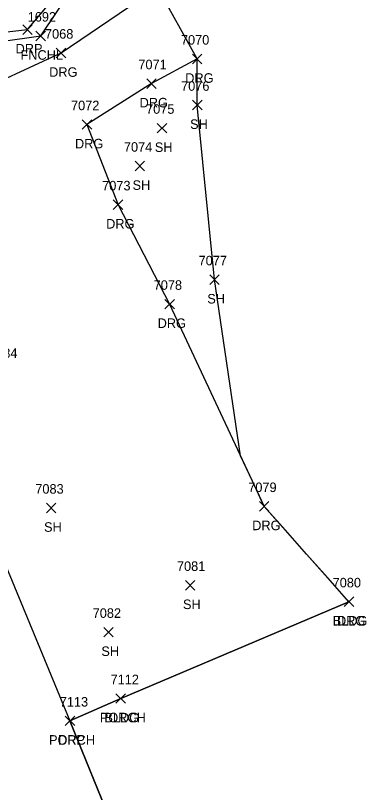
# Model space of a CAD drawing. Extents: x 1769141 to 1770911, y 735471 to 741449.
# Drawn here: x 1770390.5 to 1770464.1, y 736349.6 to 736512.6 of the extents above; entities that cross this region are included whole.
import ezdxf

# ---------------------------------------------------------------- set-up
doc = ezdxf.new("R2010")
doc.units = 0
for name, color, linetype in [('L_A', 7, 'Continuous'), ('L_I', 7, 'Continuous'), ('L_TIC', 7, 'Continuous'), ('LBC', 7, 'Continuous'), ('LBF', 7, 'Continuous'), ('LFNC', 7, 'Continuous'), ('LSOGP', 7, 'Continuous'), ('R_A', 7, 'Continuous'), ('R_I', 7, 'Continuous'), ('R_TIC', 7, 'Continuous'), ('RDG', 7, 'Continuous'), ('RDP', 7, 'Continuous')]:
    doc.layers.add(name, color=color, linetype=linetype)

msp = doc.modelspace()

# ---------------------------------------------------------------- linework, layer by layer
at = {"layer": 'L_TIC'}
for points in [[(1770394.78, 736507.31), (1770396.78, 736509.31)], [(1770396.78, 736507.31), (1770394.78, 736509.31)], [(1770427.63, 736492.8), (1770429.63, 736494.8)], [(1770429.63, 736492.8), (1770427.63, 736494.8)], [(1770420.22, 736487.97), (1770422.22, 736489.97)], [(1770422.22, 736487.97), (1770420.22, 736489.97)], [(1770415.56, 736480.02), (1770417.56, 736482.02)], [(1770417.56, 736480.02), (1770415.56, 736482.02)], [(1770431.24, 736456.18), (1770433.24, 736458.18)], [(1770433.24, 736456.18), (1770431.24, 736458.18)], [(1770396.98, 736408.29), (1770398.98, 736410.29)], [(1770398.98, 736408.29), (1770396.98, 736410.29)], [(1770426.13, 736392.08), (1770428.13, 736394.08)], [(1770428.13, 736392.08), (1770426.13, 736394.08)], [(1770459.45, 736388.63), (1770461.45, 736390.63)], [(1770461.45, 736388.63), (1770459.45, 736390.63)], [(1770409.01, 736382.24), (1770411.01, 736384.24)], [(1770411.01, 736382.24), (1770409.01, 736384.24)], [(1770411.55, 736368.32), (1770413.55, 736370.32)], [(1770413.55, 736368.32), (1770411.55, 736370.32)], [(1770411.55, 736368.32), (1770413.55, 736370.32)], [(1770413.55, 736368.32), (1770411.55, 736370.32)], [(1770400.9, 736363.63), (1770402.9, 736365.63)], [(1770402.9, 736363.63), (1770400.9, 736365.63)]]:
    msp.add_lwpolyline(points, dxfattribs=at)
at = {"layer": 'LBC'}
msp.add_lwpolyline([(1770460.45, 736389.63), (1770412.55, 736369.32)], dxfattribs=at)
at = {"layer": 'LBF'}
msp.add_lwpolyline([(1770412.55, 736369.32), (1770401.9, 736364.63), (1770411.08, 736342.09)], dxfattribs=at)
at = {"layer": 'LFNC'}
msp.add_lwpolyline([(1770354.72, 736502.49), (1770395.78, 736508.31), (1770402.62, 736518.61), (1770411.86, 736523.52)], dxfattribs=at)
at = {"layer": 'LSOGP'}
msp.add_lwpolyline([(1770411.08, 736342.09), (1770401.9, 736364.63), (1770412.55, 736369.32), (1770460.45, 736389.63), (1770456.01, 736394.63), (1770451.56, 736399.63), (1770447.11, 736404.63), (1770442.67, 736409.63), (1770440.19, 736414.94), (1770437.71, 736420.24), (1770432.24, 736457.18), (1770428.63, 736493.8), (1770428.61, 736503.48), (1770420.27, 736518.54)], dxfattribs=at)
at = {"layer": 'R_TIC'}
for points in [[(1770392.01, 736508.63), (1770394.01, 736510.63)], [(1770394.01, 736508.63), (1770392.01, 736510.63)], [(1770399.05, 736503.73), (1770401.05, 736505.73)], [(1770401.05, 736503.73), (1770399.05, 736505.73)], [(1770427.61, 736502.48), (1770429.61, 736504.48)], [(1770429.61, 736502.48), (1770427.61, 736504.48)], [(1770418.03, 736497.31), (1770420.03, 736499.31)], [(1770420.03, 736497.31), (1770418.03, 736499.31)], [(1770404.47, 736488.72), (1770406.47, 736490.72)], [(1770406.47, 736488.72), (1770404.47, 736490.72)], [(1770411.01, 736471.9), (1770413.01, 736473.9)], [(1770413.01, 736471.9), (1770411.01, 736473.9)], [(1770421.82, 736451.05), (1770423.82, 736453.05)], [(1770423.82, 736451.05), (1770421.82, 736453.05)], [(1770441.67, 736408.63), (1770443.67, 736410.63)], [(1770443.67, 736408.63), (1770441.67, 736410.63)], [(1770459.45, 736388.63), (1770461.45, 736390.63)], [(1770461.45, 736388.63), (1770459.45, 736390.63)], [(1770400.9, 736363.63), (1770402.9, 736365.63)], [(1770402.9, 736363.63), (1770400.9, 736365.63)]]:
    msp.add_lwpolyline(points, dxfattribs=at)
at = {"layer": 'RDG'}
for points in [[(1770350.83, 736500.43), (1770352.46, 736496.8), (1770366.48, 736494.7), (1770386.69, 736498.64), (1770400.05, 736504.73), (1770420.27, 736518.54)], [(1770428.61, 736503.48), (1770419.03, 736498.31), (1770405.47, 736489.72), (1770412.01, 736472.9), (1770422.82, 736452.05), (1770442.67, 736409.63), (1770460.45, 736389.63)]]:
    msp.add_lwpolyline(points, dxfattribs=at)
at = {"layer": 'RDP'}
for points in [[(1770350.59, 736502.97), (1770353.52, 736505.17), (1770393.01, 736509.63), (1770401.44, 736519.74), (1770411.18, 736524.78)], [(1770350.15, 736481.46), (1770365.5, 736480.94), (1770369.35, 736452.72), (1770376.48, 736410.11), (1770384.42, 736406.79), (1770401.9, 736364.63)]]:
    msp.add_lwpolyline(points, dxfattribs=at)

# ---------------------------------------------------------------- texts
at = {"layer": 'L_A'}
for s, p in [('FNCHL', (1770391.53, 736503.31)), ('SH', (1770427.12, 736488.8)), ('SH', (1770419.71, 736483.97)), ('SH', (1770415.05, 736476.02)), ('SH', (1770430.73, 736452.18)), ('SH', (1770396.47, 736404.29)), ('SH', (1770425.62, 736388.08)), ('BLDG', (1770457.04, 736384.63)), ('SH', (1770408.5, 736378.24)), ('PORCH', (1770408.17, 736364.32)), ('BLDG', (1770409.14, 736364.32)), ('PORCH', (1770397.52, 736359.63))]:
    msp.add_text(s, height=2, dxfattribs=at).set_placement(p)
at = {"layer": 'L_I'}
for s, p in [('1692', (1770393.04, 736511.31)), ('7076', (1770425.23, 736496.8)), ('7075', (1770417.88, 736491.97)), ('7074', (1770413.23, 736484.02)), ('7077', (1770428.9, 736460.18)), ('7084', (1770384.94, 736440.76)), ('7083', (1770394.64, 736412.29)), ('7081', (1770424.36, 736396.08)), ('7080', (1770457.03, 736392.63)), ('7082', (1770406.68, 736386.24)), ('7112', (1770410.43, 736372.32)), ('7112', (1770410.43, 736372.32)), ('7113', (1770399.77, 736367.63))]:
    msp.add_text(s, height=2, dxfattribs=at).set_placement(p)
at = {"layer": 'R_A'}
for s, p in [('DRP', (1770390.5, 736504.63)), ('DRG', (1770397.54, 736499.73)), ('DRG', (1770426.1, 736498.48)), ('DRG', (1770416.52, 736493.31)), ('DRG', (1770402.96, 736484.72)), ('DRG', (1770409.5, 736467.9)), ('DRG', (1770420.31, 736447.05)), ('DRG', (1770440.15, 736404.63)), ('DRG', (1770457.94, 736384.63)), ('DRP', (1770399.39, 736359.63))]:
    msp.add_text(s, height=2, dxfattribs=at).set_placement(p)
at = {"layer": 'R_I'}
for s, p in [('7068', (1770396.67, 736507.73)), ('7070', (1770425.19, 736506.48)), ('7071', (1770416.26, 736501.31)), ('7072', (1770402.13, 736492.72)), ('7073', (1770408.67, 736475.9)), ('7078', (1770419.48, 736455.05)), ('7079', (1770439.32, 736412.63)), ('7080', (1770457.03, 736392.63)), ('7113', (1770399.77, 736367.63))]:
    msp.add_text(s, height=2, dxfattribs=at).set_placement(p)

doc.saveas('drawing.dxf')
